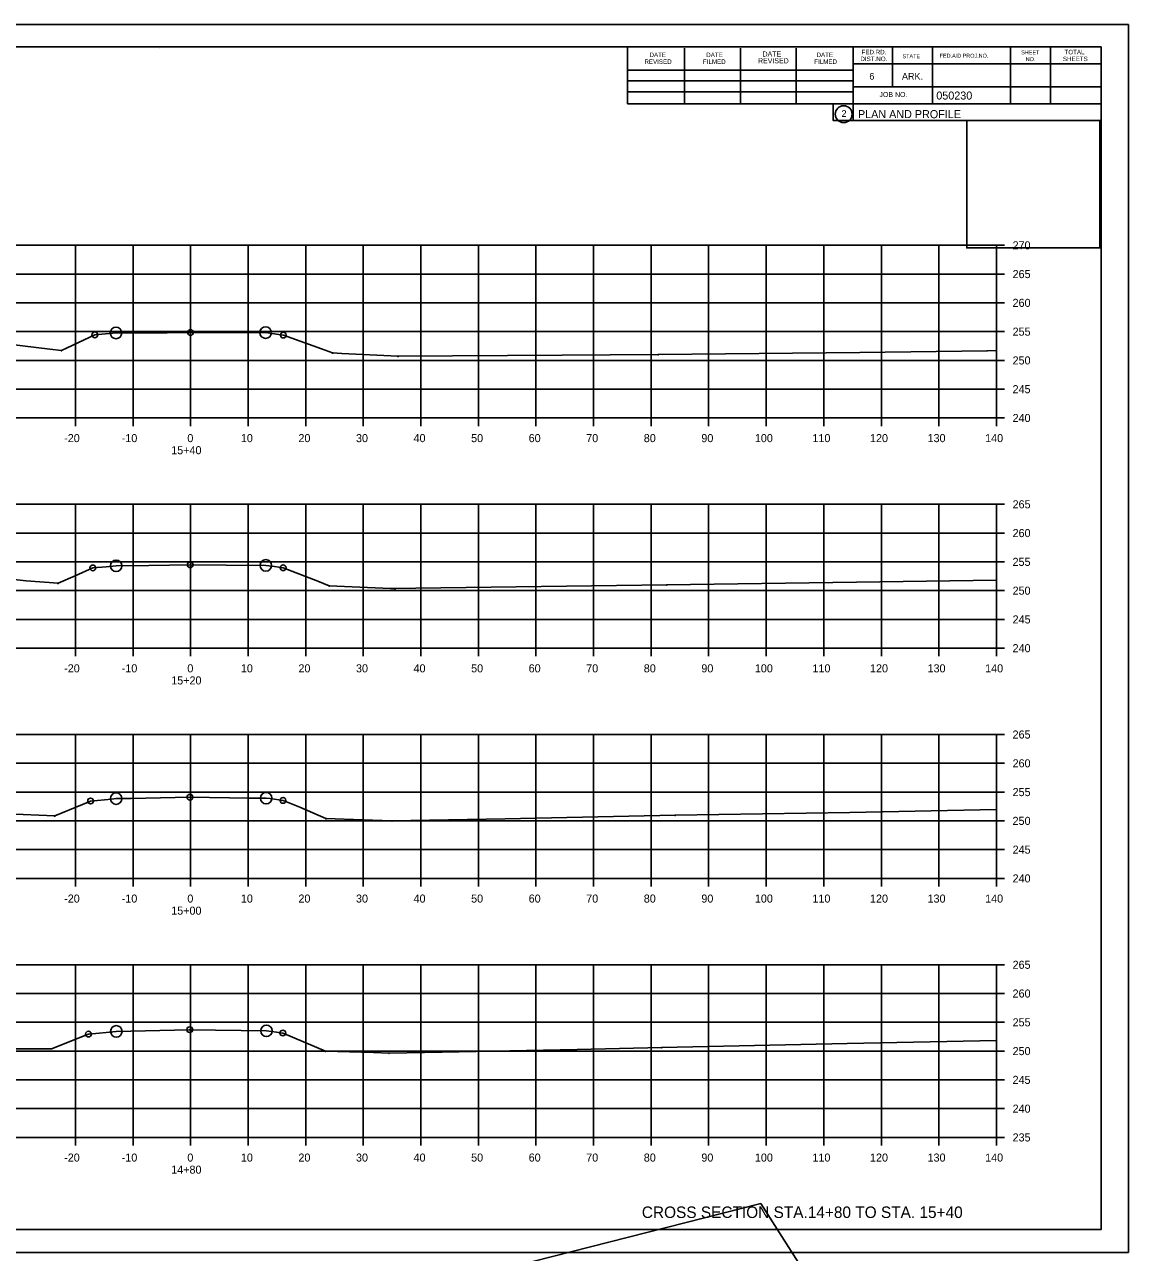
# Model space of a CAD drawing. Extents: x 1300404 to 1323571, y 234004 to 252077.
# Drawn here: x 1315688.4 to 1315880.2, y 244688.5 to 244901.9 of the extents above; entities that cross this region are included whole.
import ezdxf

# ---------------------------------------------------------------- set-up
doc = ezdxf.new("R2010")
doc.units = 0
for name, color, linetype in [('Default', 7, 'Continuous'), ('R_Axis', 7, 'Continuous'), ('R_Axis Annot', 7, 'Continuous'), ('R_Border', 7, 'Continuous'), ('R_Border Prem', 7, 'Continuous'), ('R_Draft', 7, 'Continuous'), ('R_Exist Surface', 7, 'Continuous'), ('R_Flooplain', 7, 'Continuous'), ('R_Grid', 7, 'Continuous'), ('R_No Plot', 7, 'Continuous')]:
    doc.layers.add(name, color=color, linetype=linetype)

msp = doc.modelspace()

# ---------------------------------------------------------------- linework, layer by layer
at = {"layer": 'Default'}
for p, q in [((1315559.28, 244897.96), (1315875.46, 244897.96)), ((1315793.2, 244888.08), (1315793.2, 244897.96)), ((1315803.06, 244888.08), (1315803.06, 244897.76)), ((1315812.82, 244888.08), (1315812.82, 244897.76)), ((1315822.5, 244888.08), (1315822.5, 244897.76)), ((1315832.36, 244897.96), (1315832.36, 244885.16)), ((1315839.2, 244897.96), (1315839.2, 244891.02)), ((1315846.14, 244897.96), (1315846.14, 244888.08)), ((1315859.72, 244897.96), (1315859.72, 244888.08)), ((1315866.66, 244897.96), (1315866.66, 244888.08)), ((1315875.46, 244692.5), (1315875.46, 244897.96)), ((1315875.46, 244895.02), (1315832.36, 244895.02)), ((1315875.46, 244895.04), (1315875.46, 244895.04)), ((1315793.2, 244893.94), (1315832.36, 244893.94)), ((1315793.2, 244892.08), (1315832.36, 244892.08)), ((1315875.46, 244891.02), (1315832.36, 244891.02)), ((1315835.32, 244891.02), (1315875.46, 244891.02)), ((1315793.2, 244888.08), (1315793.2, 244890.14)), ((1315793.2, 244890.14), (1315832.36, 244890.14)), ((1315875.46, 244888.08), (1315793.2, 244888.08)), ((1315832.36, 244885.16), (1315875.46, 244885.16)), ((1315875.46, 244692.5), (1315559.28, 244692.5))]:
    msp.add_line(p, q, dxfattribs=at)
msp.add_circle((1315830.74, 244886.29), 1.47, dxfattribs=at)
at = {"layer": 'R_Axis'}
for p, q in [((1315857.28, 244833.5), (1315857.28, 244863.5)), ((1315858.68, 244863.5), (1315857.28, 244863.5)), ((1315858.68, 244858.5), (1315857.28, 244858.5)), ((1315858.68, 244853.5), (1315857.28, 244853.5)), ((1315858.68, 244848.5), (1315857.28, 244848.5)), ((1315858.68, 244843.5), (1315857.28, 244843.5)), ((1315858.68, 244838.5), (1315857.28, 244838.5)), ((1315577.28, 244833.5), (1315857.28, 244833.5)), ((1315697.28, 244832.1), (1315697.28, 244833.5)), ((1315707.28, 244832.1), (1315707.28, 244833.5)), ((1315717.28, 244832.1), (1315717.28, 244833.5)), ((1315727.28, 244832.1), (1315727.28, 244833.5)), ((1315737.28, 244832.1), (1315737.28, 244833.5)), ((1315747.28, 244832.1), (1315747.28, 244833.5)), ((1315757.28, 244832.1), (1315757.28, 244833.5)), ((1315767.28, 244832.1), (1315767.28, 244833.5)), ((1315777.28, 244832.1), (1315777.28, 244833.5)), ((1315787.28, 244832.1), (1315787.28, 244833.5)), ((1315797.28, 244832.1), (1315797.28, 244833.5)), ((1315807.28, 244832.1), (1315807.28, 244833.5)), ((1315817.28, 244832.1), (1315817.28, 244833.5)), ((1315827.28, 244832.1), (1315827.28, 244833.5)), ((1315837.28, 244832.1), (1315837.28, 244833.5)), ((1315847.28, 244832.1), (1315847.28, 244833.5)), ((1315857.28, 244832.1), (1315857.28, 244833.5)), ((1315858.68, 244833.5), (1315857.28, 244833.5)), ((1315857.28, 244793.5), (1315857.28, 244818.5)), ((1315858.68, 244818.5), (1315857.28, 244818.5)), ((1315858.68, 244813.5), (1315857.28, 244813.5)), ((1315858.68, 244808.5), (1315857.28, 244808.5)), ((1315858.68, 244803.5), (1315857.28, 244803.5)), ((1315858.68, 244798.5), (1315857.28, 244798.5)), ((1315577.28, 244793.5), (1315857.28, 244793.5)), ((1315697.28, 244792.1), (1315697.28, 244793.5)), ((1315707.28, 244792.1), (1315707.28, 244793.5)), ((1315717.28, 244792.1), (1315717.28, 244793.5)), ((1315727.28, 244792.1), (1315727.28, 244793.5)), ((1315737.28, 244792.1), (1315737.28, 244793.5)), ((1315747.28, 244792.1), (1315747.28, 244793.5)), ((1315757.28, 244792.1), (1315757.28, 244793.5)), ((1315767.28, 244792.1), (1315767.28, 244793.5)), ((1315777.28, 244792.1), (1315777.28, 244793.5)), ((1315787.28, 244792.1), (1315787.28, 244793.5)), ((1315797.28, 244792.1), (1315797.28, 244793.5)), ((1315807.28, 244792.1), (1315807.28, 244793.5)), ((1315817.28, 244792.1), (1315817.28, 244793.5)), ((1315827.28, 244792.1), (1315827.28, 244793.5)), ((1315837.28, 244792.1), (1315837.28, 244793.5)), ((1315847.28, 244792.1), (1315847.28, 244793.5)), ((1315857.28, 244792.1), (1315857.28, 244793.5)), ((1315858.68, 244793.5), (1315857.28, 244793.5)), ((1315857.28, 244753.5), (1315857.28, 244778.5)), ((1315858.68, 244778.5), (1315857.28, 244778.5)), ((1315858.68, 244773.5), (1315857.28, 244773.5)), ((1315858.68, 244768.5), (1315857.28, 244768.5)), ((1315858.68, 244763.5), (1315857.28, 244763.5)), ((1315858.68, 244758.5), (1315857.28, 244758.5)), ((1315577.28, 244753.5), (1315857.28, 244753.5)), ((1315697.28, 244752.1), (1315697.28, 244753.5)), ((1315707.28, 244752.1), (1315707.28, 244753.5)), ((1315717.28, 244752.1), (1315717.28, 244753.5)), ((1315727.28, 244752.1), (1315727.28, 244753.5)), ((1315737.28, 244752.1), (1315737.28, 244753.5)), ((1315747.28, 244752.1), (1315747.28, 244753.5)), ((1315757.28, 244752.1), (1315757.28, 244753.5)), ((1315767.28, 244752.1), (1315767.28, 244753.5)), ((1315777.28, 244752.1), (1315777.28, 244753.5)), ((1315787.28, 244752.1), (1315787.28, 244753.5)), ((1315797.28, 244752.1), (1315797.28, 244753.5)), ((1315807.28, 244752.1), (1315807.28, 244753.5)), ((1315817.28, 244752.1), (1315817.28, 244753.5)), ((1315827.28, 244752.1), (1315827.28, 244753.5)), ((1315837.28, 244752.1), (1315837.28, 244753.5)), ((1315847.28, 244752.1), (1315847.28, 244753.5)), ((1315857.28, 244752.1), (1315857.28, 244753.5)), ((1315858.68, 244753.5), (1315857.28, 244753.5)), ((1315857.28, 244708.5), (1315857.28, 244738.5)), ((1315858.68, 244738.5), (1315857.28, 244738.5)), ((1315858.68, 244733.5), (1315857.28, 244733.5)), ((1315858.68, 244728.5), (1315857.28, 244728.5)), ((1315858.68, 244723.5), (1315857.28, 244723.5)), ((1315858.68, 244718.5), (1315857.28, 244718.5)), ((1315858.68, 244713.5), (1315857.28, 244713.5)), ((1315577.28, 244708.5), (1315857.28, 244708.5)), ((1315697.28, 244707.1), (1315697.28, 244708.5)), ((1315707.28, 244707.1), (1315707.28, 244708.5)), ((1315717.28, 244707.1), (1315717.28, 244708.5)), ((1315727.28, 244707.1), (1315727.28, 244708.5)), ((1315737.28, 244707.1), (1315737.28, 244708.5)), ((1315747.28, 244707.1), (1315747.28, 244708.5)), ((1315757.28, 244707.1), (1315757.28, 244708.5)), ((1315767.28, 244707.1), (1315767.28, 244708.5)), ((1315777.28, 244707.1), (1315777.28, 244708.5)), ((1315787.28, 244707.1), (1315787.28, 244708.5)), ((1315797.28, 244707.1), (1315797.28, 244708.5)), ((1315807.28, 244707.1), (1315807.28, 244708.5)), ((1315817.28, 244707.1), (1315817.28, 244708.5)), ((1315827.28, 244707.1), (1315827.28, 244708.5)), ((1315837.28, 244707.1), (1315837.28, 244708.5)), ((1315847.28, 244707.1), (1315847.28, 244708.5)), ((1315857.28, 244707.1), (1315857.28, 244708.5)), ((1315858.68, 244708.5), (1315857.28, 244708.5))]:
    msp.add_line(p, q, dxfattribs=at)
at = {"layer": 'R_Border'}
msp.add_line((1315711.8, 244897.7), (1315711.8, 244897.7), dxfattribs=at)
msp.add_line((1315711.8, 244897.7), (1315711.8, 244897.7), dxfattribs=at)
at = {"layer": 'R_Draft'}
for points in [[(1315694.83, 244845.28), (1315694.88, 244845.18), (1315694.78, 244845.18)], [(1315741.95, 244844.85), (1315742, 244844.75), (1315741.9, 244844.75)], [(1315753.29, 244844.27), (1315753.34, 244844.17), (1315753.24, 244844.17)], [(1315798.52, 244844.59), (1315798.57, 244844.49), (1315798.47, 244844.49)], [(1315855.65, 244845.24), (1315855.7, 244845.14), (1315855.6, 244845.14)], [(1315694.25, 244804.84), (1315694.3, 244804.74), (1315694.2, 244804.74)], [(1315741.37, 244804.4), (1315741.42, 244804.3), (1315741.32, 244804.3)], [(1315752.78, 244803.91), (1315752.83, 244803.81), (1315752.73, 244803.81)], [(1315800, 244804.57), (1315800.05, 244804.47), (1315799.95, 244804.47)], [(1315693.67, 244764.4), (1315693.72, 244764.3), (1315693.62, 244764.3)], [(1315740.79, 244763.95), (1315740.84, 244763.85), (1315740.74, 244763.85)], [(1315752.26, 244763.56), (1315752.31, 244763.46), (1315752.21, 244763.46)], [(1315801.48, 244764.54), (1315801.53, 244764.44), (1315801.43, 244764.44)], [(1315799.14, 244724.17), (1315799.19, 244724.07), (1315799.09, 244724.07)], [(1315693.12, 244723.97), (1315693.17, 244723.87), (1315693.07, 244723.87)], [(1315740.71, 244723.52), (1315740.76, 244723.42), (1315740.66, 244723.42)], [(1315751.75, 244723.2), (1315751.8, 244723.1), (1315751.7, 244723.1)]]:
    msp.add_lwpolyline(points, close=True, dxfattribs=at)
at = {"layer": 'R_Exist Surface'}
for points in [[(1315682.79, 244846.67), (1315692.82, 244845.44), (1315694.83, 244845.23), (1315695.86, 244845.69), (1315700.64, 244847.95), (1315701.85, 244848.05), (1315704.32, 244848.27), (1315713.22, 244848.32), (1315717.27, 244848.35), (1315726.77, 244848.35), (1315730.31, 244848.33), (1315732.59, 244848.01), (1315733.39, 244847.9), (1315740.02, 244845.49), (1315741.95, 244844.8), (1315743.53, 244844.71), (1315753.29, 244844.22), (1315781.83, 244844.39), (1315798.52, 244844.54), (1315833.56, 244844.89), (1315855.65, 244845.19), (1315857.28, 244845.21)], [(1315683.89, 244805.7), (1315688.72, 244805.22), (1315694.25, 244804.79), (1315697.24, 244806.08), (1315700.27, 244807.45), (1315702.62, 244807.66), (1315704.34, 244807.82), (1315710.04, 244807.87), (1315717.22, 244807.98), (1315723.46, 244807.95), (1315730.36, 244807.89), (1315731.83, 244807.69), (1315733.36, 244807.48), (1315739.37, 244805.16), (1315741.37, 244804.35), (1315751.98, 244803.89), (1315752.78, 244803.86), (1315756.42, 244803.93), (1315800, 244804.52), (1315832.96, 244804.95), (1315857.28, 244805.34)], [(1315685.39, 244764.71), (1315693.67, 244764.35), (1315698.5, 244766.35), (1315699.9, 244766.95), (1315703.51, 244767.29), (1315704.35, 244767.37), (1315706.96, 244767.41), (1315717.17, 244767.6), (1315727.46, 244767.47), (1315730.4, 244767.45), (1315731.09, 244767.36), (1315733.33, 244767.06), (1315736.25, 244765.86), (1315740.79, 244763.9), (1315747.21, 244763.7), (1315752.26, 244763.51), (1315771.9, 244763.85), (1315801.48, 244764.49), (1315831.79, 244764.98), (1315857.28, 244765.46)], [(1315685.7, 244723.92), (1315692.19, 244723.92), (1315693.12, 244723.92), (1315699.37, 244726.39), (1315699.53, 244726.45), (1315699.64, 244726.46), (1315704.37, 244726.92), (1315717.02, 244727.21), (1315717.12, 244727.22), (1315717.22, 244727.22), (1315730.45, 244727.01), (1315732.19, 244726.78), (1315733.3, 244726.64), (1315733.5, 244726.55), (1315740.71, 244723.47), (1315749.05, 244723.23), (1315751.75, 244723.15), (1315760.99, 244723.33), (1315784.42, 244723.78), (1315799.14, 244724.12), (1315831.35, 244724.84), (1315857.28, 244725.35)]]:
    msp.add_lwpolyline(points, dxfattribs=at)
at = {"layer": 'R_Flooplain'}
for p, q in [((1315816.34, 244696.99), (1315688.91, 244664.69)), ((1315861.24, 244626.98), (1315816.34, 244696.99))]:
    msp.add_line(p, q, dxfattribs=at)
at = {"layer": 'R_Grid'}
for p, q in [((1315577.28, 244863.5), (1315857.28, 244863.5)), ((1315697.28, 244833.5), (1315697.28, 244863.5)), ((1315707.28, 244833.5), (1315707.28, 244863.5)), ((1315717.28, 244833.5), (1315717.28, 244863.5)), ((1315727.28, 244833.5), (1315727.28, 244863.5)), ((1315737.28, 244833.5), (1315737.28, 244863.5)), ((1315747.28, 244833.5), (1315747.28, 244863.5)), ((1315757.28, 244833.5), (1315757.28, 244863.5)), ((1315767.28, 244833.5), (1315767.28, 244863.5)), ((1315777.28, 244833.5), (1315777.28, 244863.5)), ((1315787.28, 244833.5), (1315787.28, 244863.5)), ((1315797.28, 244833.5), (1315797.28, 244863.5)), ((1315807.28, 244833.5), (1315807.28, 244863.5)), ((1315817.28, 244833.5), (1315817.28, 244863.5)), ((1315827.28, 244833.5), (1315827.28, 244863.5)), ((1315837.28, 244833.5), (1315837.28, 244863.5)), ((1315847.28, 244833.5), (1315847.28, 244863.5)), ((1315857.28, 244833.5), (1315857.28, 244863.5)), ((1315577.28, 244858.5), (1315857.28, 244858.5)), ((1315577.28, 244853.5), (1315857.28, 244853.5)), ((1315577.28, 244848.5), (1315857.28, 244848.5)), ((1315577.28, 244843.5), (1315857.28, 244843.5)), ((1315577.28, 244838.5), (1315857.28, 244838.5)), ((1315577.28, 244833.5), (1315857.28, 244833.5)), ((1315577.28, 244818.5), (1315857.28, 244818.5)), ((1315697.28, 244793.5), (1315697.28, 244818.5)), ((1315707.28, 244793.5), (1315707.28, 244818.5)), ((1315717.28, 244793.5), (1315717.28, 244818.5)), ((1315727.28, 244793.5), (1315727.28, 244818.5)), ((1315737.28, 244793.5), (1315737.28, 244818.5)), ((1315747.28, 244793.5), (1315747.28, 244818.5)), ((1315757.28, 244793.5), (1315757.28, 244818.5)), ((1315767.28, 244793.5), (1315767.28, 244818.5)), ((1315777.28, 244793.5), (1315777.28, 244818.5)), ((1315787.28, 244793.5), (1315787.28, 244818.5)), ((1315797.28, 244793.5), (1315797.28, 244818.5)), ((1315807.28, 244793.5), (1315807.28, 244818.5)), ((1315817.28, 244793.5), (1315817.28, 244818.5)), ((1315827.28, 244793.5), (1315827.28, 244818.5)), ((1315837.28, 244793.5), (1315837.28, 244818.5)), ((1315847.28, 244793.5), (1315847.28, 244818.5)), ((1315857.28, 244793.5), (1315857.28, 244818.5)), ((1315577.28, 244813.5), (1315857.28, 244813.5)), ((1315577.28, 244808.5), (1315857.28, 244808.5)), ((1315577.28, 244803.5), (1315857.28, 244803.5)), ((1315577.28, 244798.5), (1315857.28, 244798.5)), ((1315577.28, 244793.5), (1315857.28, 244793.5)), ((1315577.28, 244778.5), (1315857.28, 244778.5)), ((1315697.28, 244753.5), (1315697.28, 244778.5)), ((1315707.28, 244753.5), (1315707.28, 244778.5)), ((1315717.28, 244753.5), (1315717.28, 244778.5)), ((1315727.28, 244753.5), (1315727.28, 244778.5)), ((1315737.28, 244753.5), (1315737.28, 244778.5)), ((1315747.28, 244753.5), (1315747.28, 244778.5)), ((1315757.28, 244753.5), (1315757.28, 244778.5)), ((1315767.28, 244753.5), (1315767.28, 244778.5)), ((1315777.28, 244753.5), (1315777.28, 244778.5)), ((1315787.28, 244753.5), (1315787.28, 244778.5)), ((1315797.28, 244753.5), (1315797.28, 244778.5)), ((1315807.28, 244753.5), (1315807.28, 244778.5)), ((1315817.28, 244753.5), (1315817.28, 244778.5)), ((1315827.28, 244753.5), (1315827.28, 244778.5)), ((1315837.28, 244753.5), (1315837.28, 244778.5)), ((1315847.28, 244753.5), (1315847.28, 244778.5)), ((1315857.28, 244753.5), (1315857.28, 244778.5)), ((1315577.28, 244773.5), (1315857.28, 244773.5)), ((1315577.28, 244768.5), (1315857.28, 244768.5)), ((1315577.28, 244763.5), (1315857.28, 244763.5)), ((1315577.28, 244758.5), (1315857.28, 244758.5)), ((1315577.28, 244753.5), (1315857.28, 244753.5)), ((1315577.28, 244738.5), (1315857.28, 244738.5)), ((1315697.28, 244708.5), (1315697.28, 244738.5)), ((1315707.28, 244708.5), (1315707.28, 244738.5)), ((1315717.28, 244708.5), (1315717.28, 244738.5)), ((1315727.28, 244708.5), (1315727.28, 244738.5)), ((1315737.28, 244708.5), (1315737.28, 244738.5)), ((1315747.28, 244708.5), (1315747.28, 244738.5)), ((1315757.28, 244708.5), (1315757.28, 244738.5)), ((1315767.28, 244708.5), (1315767.28, 244738.5)), ((1315777.28, 244708.5), (1315777.28, 244738.5)), ((1315787.28, 244708.5), (1315787.28, 244738.5)), ((1315797.28, 244708.5), (1315797.28, 244738.5)), ((1315807.28, 244708.5), (1315807.28, 244738.5)), ((1315817.28, 244708.5), (1315817.28, 244738.5)), ((1315827.28, 244708.5), (1315827.28, 244738.5)), ((1315837.28, 244708.5), (1315837.28, 244738.5)), ((1315847.28, 244708.5), (1315847.28, 244738.5)), ((1315857.28, 244708.5), (1315857.28, 244738.5)), ((1315577.28, 244733.5), (1315857.28, 244733.5)), ((1315577.28, 244728.5), (1315857.28, 244728.5)), ((1315577.28, 244723.5), (1315857.28, 244723.5)), ((1315577.28, 244718.5), (1315857.28, 244718.5)), ((1315577.28, 244713.5), (1315857.28, 244713.5)), ((1315577.28, 244708.5), (1315857.28, 244708.5))]:
    msp.add_line(p, q, dxfattribs=at)
at = {"layer": 'R_No Plot'}
for p, q in [((1315546.87, 244901.85), (1315880.21, 244901.85)), ((1315546.87, 244688.52), (1315880.21, 244688.52))]:
    msp.add_line(p, q, dxfattribs=at)
for points in [[(1315546.87, 244901.85), (1315880.21, 244901.85), (1315880.21, 244688.52), (1315546.87, 244688.52)], [(1315793.2, 244897.96), (1315793.2, 244888.08), (1315828.93, 244888.08), (1315828.93, 244885.16), (1315852.13, 244885.16), (1315852.13, 244863.04), (1315875.46, 244863.04), (1315875.46, 244692.5), (1315559.28, 244692.5), (1315559.28, 244897.96)], [(1315852.13, 244885.19), (1315875.23, 244885.19), (1315875.23, 244863.04), (1315852.13, 244863.04)]]:
    msp.add_lwpolyline(points, close=True, dxfattribs=at)
for centre, radius in [((1315700.64, 244847.95), 0.5), ((1315704.32, 244848.27), 1), ((1315717.27, 244848.35), 0.5), ((1315730.31, 244848.33), 1), ((1315733.39, 244847.9), 0.5), ((1315700.27, 244807.45), 0.5), ((1315704.34, 244807.82), 1), ((1315717.22, 244807.98), 0.5), ((1315730.36, 244807.89), 1), ((1315733.36, 244807.48), 0.5), ((1315699.9, 244766.95), 0.5), ((1315704.35, 244767.37), 1), ((1315717.17, 244767.6), 0.5), ((1315730.4, 244767.45), 1), ((1315733.33, 244767.06), 0.5), ((1315699.53, 244726.45), 0.5), ((1315704.37, 244726.92), 1), ((1315717.12, 244727.22), 0.5), ((1315730.45, 244727.01), 1), ((1315733.3, 244726.64), 0.5)]:
    msp.add_circle(centre, radius, dxfattribs=at)

# ---------------------------------------------------------------- texts
at = {"layer": 'Default'}
msp.add_text('2', height=1.17, dxfattribs=at).set_placement((1315830.36, 244885.81))
at = {"layer": 'R_Axis Annot'}
for s, p in [('270', (1315860.08, 244862.8)), ('265', (1315860.08, 244857.8)), ('260', (1315860.08, 244852.8)), ('255', (1315860.08, 244847.8)), ('250', (1315860.08, 244842.8)), ('245', (1315860.08, 244837.8)), ('240', (1315860.08, 244832.8)), ('-20', (1315695.31, 244829.3)), ('-10', (1315705.31, 244829.3)), ('15+40', (1315713.91, 244827.2)), ('0', (1315716.71, 244829.3)), ('10', (1315726.01, 244829.3)), ('20', (1315736.01, 244829.3)), ('30', (1315746.01, 244829.3)), ('40', (1315756.01, 244829.3)), ('50', (1315766.01, 244829.3)), ('60', (1315776.01, 244829.3)), ('70', (1315786.01, 244829.3)), ('80', (1315796.01, 244829.3)), ('90', (1315806.01, 244829.3)), ('100', (1315815.31, 244829.3)), ('110', (1315825.31, 244829.3)), ('120', (1315835.31, 244829.3)), ('130', (1315845.31, 244829.3)), ('140', (1315855.31, 244829.3)), ('265', (1315860.08, 244817.8)), ('260', (1315860.08, 244812.8)), ('255', (1315860.08, 244807.8)), ('250', (1315860.08, 244802.8)), ('245', (1315860.08, 244797.8)), ('240', (1315860.08, 244792.8)), ('-20', (1315695.31, 244789.3)), ('-10', (1315705.31, 244789.3)), ('0', (1315716.71, 244789.3)), ('10', (1315726.01, 244789.3)), ('20', (1315736.01, 244789.3)), ('30', (1315746.01, 244789.3)), ('40', (1315756.01, 244789.3)), ('50', (1315766.01, 244789.3)), ('60', (1315776.01, 244789.3)), ('70', (1315786.01, 244789.3)), ('80', (1315796.01, 244789.3)), ('90', (1315806.01, 244789.3)), ('100', (1315815.31, 244789.3)), ('110', (1315825.31, 244789.3)), ('120', (1315835.31, 244789.3)), ('130', (1315845.31, 244789.3)), ('140', (1315855.31, 244789.3)), ('15+20', (1315713.91, 244787.2)), ('265', (1315860.08, 244777.8)), ('260', (1315860.08, 244772.8)), ('255', (1315860.08, 244767.8)), ('250', (1315860.08, 244762.8)), ('245', (1315860.08, 244757.8)), ('240', (1315860.08, 244752.8)), ('-20', (1315695.31, 244749.3)), ('-10', (1315705.31, 244749.3)), ('0', (1315716.71, 244749.3)), ('10', (1315726.01, 244749.3)), ('20', (1315736.01, 244749.3)), ('30', (1315746.01, 244749.3)), ('40', (1315756.01, 244749.3)), ('50', (1315766.01, 244749.3)), ('60', (1315776.01, 244749.3)), ('70', (1315786.01, 244749.3)), ('80', (1315796.01, 244749.3)), ('90', (1315806.01, 244749.3)), ('100', (1315815.31, 244749.3)), ('110', (1315825.31, 244749.3)), ('120', (1315835.31, 244749.3)), ('130', (1315845.31, 244749.3)), ('140', (1315855.31, 244749.3)), ('15+00', (1315713.91, 244747.2)), ('265', (1315860.08, 244737.8)), ('260', (1315860.08, 244732.8)), ('255', (1315860.08, 244727.8)), ('250', (1315860.08, 244722.8)), ('245', (1315860.08, 244717.8)), ('240', (1315860.08, 244712.8)), ('235', (1315860.08, 244707.8)), ('-20', (1315695.31, 244704.3)), ('-10', (1315705.31, 244704.3)), ('0', (1315716.71, 244704.3)), ('10', (1315726.01, 244704.3)), ('20', (1315736.01, 244704.3)), ('30', (1315746.01, 244704.3)), ('40', (1315756.01, 244704.3)), ('50', (1315766.01, 244704.3)), ('60', (1315776.01, 244704.3)), ('70', (1315786.01, 244704.3)), ('80', (1315796.01, 244704.3)), ('90', (1315806.01, 244704.3)), ('100', (1315815.31, 244704.3)), ('110', (1315825.31, 244704.3)), ('120', (1315835.31, 244704.3)), ('130', (1315845.31, 244704.3)), ('140', (1315855.31, 244704.3)), ('14+80', (1315713.91, 244702.2))]:
    msp.add_text(s, height=1.4, dxfattribs=at).set_placement(p)
at = {"layer": 'R_Border'}
for s, height, p in [('DATE', 0.782, (1315797, 244896.2)), ('DATE', 0.782, (1315806.86, 244896.2)), ('DATE', 0.879, (1315816.64, 244896.3)), ('DATE', 0.782, (1315826.02, 244896.2)), ('FED.RD.', 0.782, (1315833.84, 244896.68)), ('SHEET', 0.684, (1315861.58, 244896.68)), ('TOTAL', 0.782, (1315869.1, 244896.68)), ('REVISED', 0.782, (1315796.12, 244895.02)), ('FILMED', 0.782, (1315806.28, 244895.02)), ('REVISED', 0.879, (1315815.86, 244895.12)), ('FILMED', 0.782, (1315825.62, 244895.02)), ('DIST.NO.', 0.782, (1315833.64, 244895.5)), ('STATE', 0.684, (1315840.96, 244896)), ('FED.AID PROJ.NO.', 0.684, (1315847.42, 244896.1)), ('NO.', 0.684, (1315862.36, 244895.5)), ('SHEETS', 0.782, (1315868.82, 244895.5)), ('6', 1.17, (1315835.2, 244892.28)), ('ARK.', 1.172, (1315840.86, 244892.28)), ('JOB NO.', 0.879, (1315836.96, 244889.26))]:
    msp.add_text(s, height=height, dxfattribs=at).set_placement(p)
for s, p in [('050230', (1315846.83, 244888.82)), ('PLAN AND PROFILE', (1315833.22, 244885.59))]:
    msp.add_text(s, height=1.4, rotation=360, dxfattribs=at).set_placement(p)
at = {"layer": 'R_Border Prem'}
msp.add_text('DWB', height=0.01, dxfattribs=at).set_placement((1315836.15, 244879.47))
at = {"layer": 'R_Draft'}
msp.add_text('CROSS SECTION STA.14+80 TO STA. 15+40', height=2, dxfattribs=at).set_placement((1315795.67, 244694.5))

doc.saveas('drawing.dxf')
